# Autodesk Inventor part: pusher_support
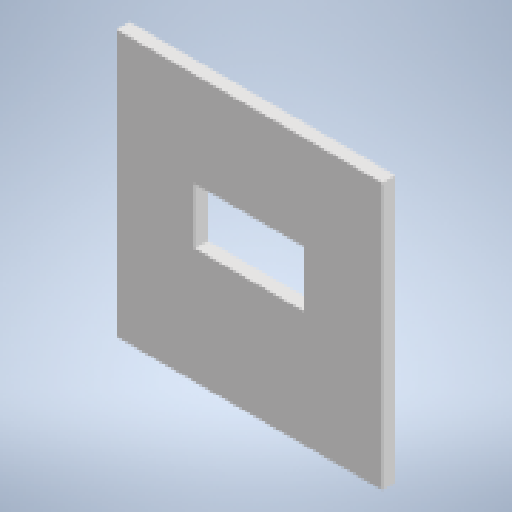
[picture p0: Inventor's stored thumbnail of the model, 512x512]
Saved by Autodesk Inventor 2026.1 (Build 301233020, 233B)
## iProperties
Created: 2026-10
Part Number: pusher_support
Material: Generic
Document SubType Name: Modeling
Designer: alolo
Density: 1 g/cm^3
Appearance: Default
Author: alolo
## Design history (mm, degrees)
sketch "Sketch1"
  geometry: L1 (0, 0)-(41, 0); L2 (41, 0)-(41, 21); L3 (41, 21)-(0, 21); L4 (0, 21)-(0, 0); L5 (20.5, 0)-(20.5, 21); L6 (-29.5, 56.5)-(70.5, 56.5); L7 (70.5, 56.5)-(70.5, -43.5); L8 (70.5, -43.5)-(-29.5, -43.5); L9 (-29.5, -43.5)-(-29.5, 56.5); C1 r 2.2 at (-5, 6.5); C2 r 2.2 at (-5, 15.5); C3 r 2.2 at (46, 6.5); C4 r 2.2 at (46, 15.5); 1 further point
  constraints: 18 end point, 4 centre point, 4 parallel, 3 midpoint, 2 horizontal, 2 perpendicular, 2 symmetric about line, 2 vertical alignment, 2 other
  dimensions: "d0" = 41 distance of L3.end L2.end; "d1" = 4.4 diameter of C1; "d2" = 21 distance of L1.end L2.end; "d3" = 5 distance from line of L4 C1.centre; "d4" = 14.5 distance from line of L3 C1.centre; "d5" = 4.4 diameter of C2; "d6" = 5.5 distance from line of L3 C2.centre; "d7" = 100 distance of L6.end L7.end; "d8" = 43.5 distance between parallel lines of L1 L8; "d9" = 100 distance of L6.start L6.end
extrude "Extrusion1" new body sketch "Sketch1" distance "d10" = 5 (= wood_thickness); taper "d11" = 0 deg
sketch "Sketch2"
  geometry: 4 further points
hole "Hole1" sketch "Sketch2" at (-4.3, 14.5), (-4.3, 5.5), (46, 14.5), (46, 5.5) diameter "d12" = 4.5; stored, may be unused: countersink angle "d16" = 90 deg, drill point angle "d18" = 0 deg; dims "d13" = 6, "d14" = 4, "d15" = 2, "d17" = 8
sketch "Sketch3"
  geometry: 2 further points
hole "Hole2" sketch "Sketch3" at (-28.5, -33.5), (-12.5, -33.5) diameter "d19" = 4.5; stored, may be unused: countersink angle "d23" = 90 deg, drill point angle "d25" = 0 deg; dims "d20" = 6, "d21" = 4, "d22" = 2, "d24" = 8
body "Solid1"
other parameters: "slide_length" = 195 [user parameter], "slide_angle" = 7 deg [user parameter], "slide_width" = 65 [user parameter], "wood_thickness" = 5 [user parameter; used in 1 equation term], "aclyric_thickness" = 6 [user parameter]
